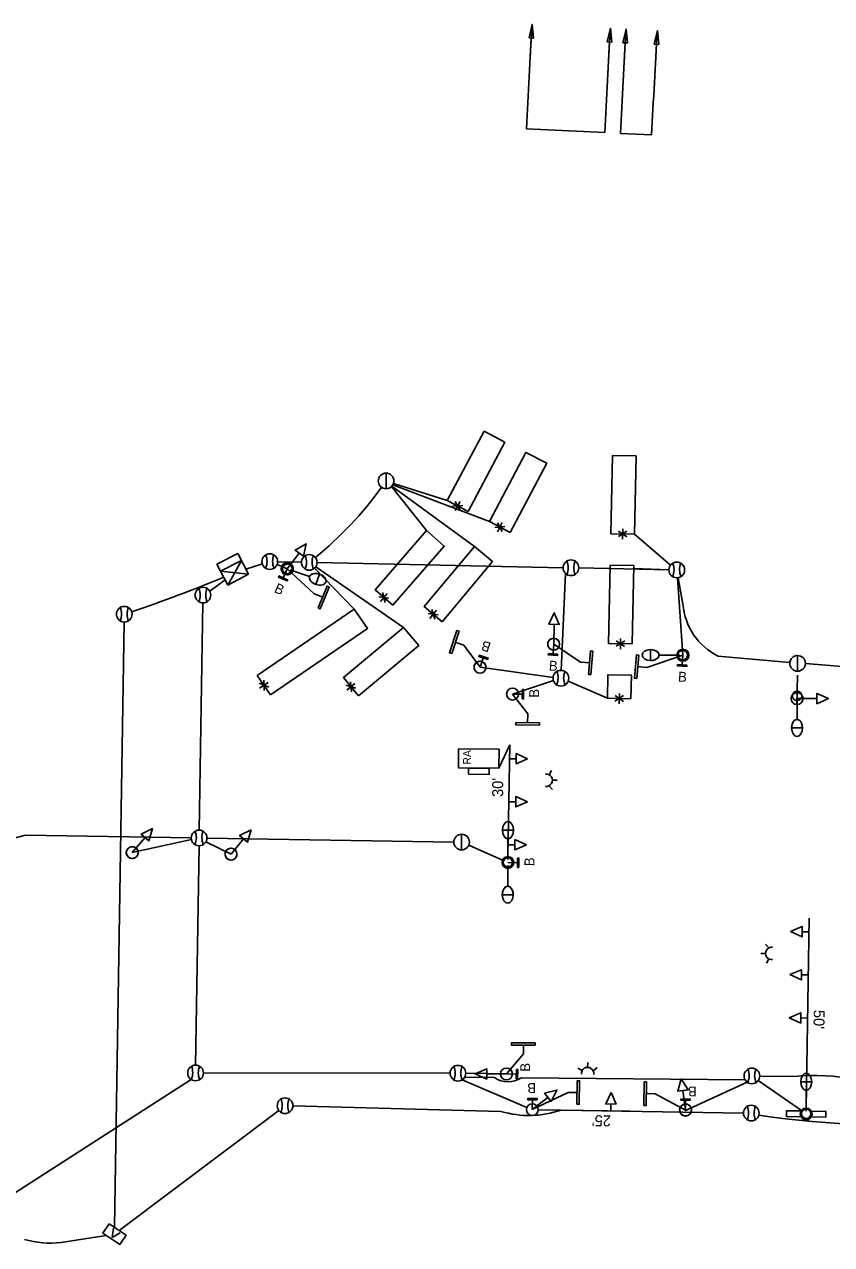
# Model space of a CAD drawing. Extents: x 596176 to 605330, y 332416 to 402398.
# Drawn here: x 602517.5 to 602723.5, y 366044.3 to 366355.8 of the extents above; entities that cross this region are included whole.
import ezdxf

# ---------------------------------------------------------------- set-up
doc = ezdxf.new("R2010")
doc.units = 0
for name, color, linetype in [('P_LTG', 7, 'Continuous'), ('P_SIG', 7, 'Continuous'), ('P_SIG_Bold', 7, 'Continuous'), ('P_SIG_Conduit', 7, 'Continuous'), ('P_SIG_IC', 7, 'Continuous'), ('P_SIG_Loops', 7, 'Continuous')]:
    doc.layers.add(name, color=color, linetype=linetype)

# ---------------------------------------------------------------- blocks, each defined once
blk = doc.blocks.new('_U322')
at = {"layer": 'P_LTG'}
for p, q in [((4.32, 25.12), (-4.14, 25.12)), ((0.05, 2.3), (0.05, 18.44))]:
    blk.add_line(p, q, dxfattribs=at)
blk.add_circle((0.05, 0.15), 3.68, dxfattribs=at)
blk.add_ellipse((0.09, 25.12), major_axis=(0, 6.65), ratio=0.636439, dxfattribs=at)
blk.add_ellipse((0.09, 25.12), major_axis=(0, 6.65), ratio=0.636439, start_param=1.570796, end_param=4.712389, dxfattribs=at)

msp = doc.modelspace()

# ---------------------------------------------------------------- linework, layer by layer
at = {"layer": 'P_SIG'}
for p, q in [((602609.8, 366241.29), (602609.78, 366237.29)), ((602566.64, 366218.02), (602571.96, 366220.79)), ((602566.64, 366218.02), (602571.96, 366220.79)), ((602567.56, 366216.24), (602572.88, 366219.01)), ((602567.56, 366216.24), (602572.88, 366219.01)), ((602569.41, 366212.7), (602572.88, 366219.01)), ((602569.41, 366212.7), (602572.88, 366219.01)), ((602571.96, 366220.79), (602574.73, 366215.46)), ((602571.96, 366220.79), (602574.73, 366215.46)), ((602587.64, 366220.85), (602584.56, 366216.84)), ((602569.41, 366212.7), (602566.64, 366218.02)), ((602569.41, 366212.7), (602566.64, 366218.02)), ((602574.73, 366215.46), (602567.56, 366216.24)), ((602574.73, 366215.46), (602567.56, 366216.24)), ((602584.56, 366216.84), (602583.55, 366214.55)), ((602591.47, 366210.49), (602584.56, 366216.84)), ((602574.73, 366215.46), (602569.41, 366212.7)), ((602574.73, 366215.46), (602569.41, 366212.7)), ((602591.47, 366210.49), (602593.69, 366209.57)), ((602652.66, 366202.66), (602652.57, 366197.61)), ((602629.66, 366197.38), (602627.39, 366198.16)), ((602629.66, 366197.38), (602633.78, 366191.72)), ((602652.57, 366197.61), (602652.4, 366195.11)), ((602659.4, 366193.02), (602652.57, 366197.61)), ((602633.78, 366191.72), (602634.58, 366194.08)), ((602676.31, 366191.69), (602685.53, 366194.79)), ((602685.53, 366194.79), (602685.35, 366192.3)), ((602714.81, 366194.71), (602714.79, 366190.71)), ((602659.4, 366193.02), (602661.79, 366192.82)), ((602676.31, 366191.69), (602673.92, 366191.91)), ((602642.06, 366184.86), (602644.56, 366184.82)), ((602645.93, 366179.8), (602642.06, 366184.86)), ((602719.73, 366183.7), (602714.67, 366183.71)), ((602645.93, 366179.8), (602645.9, 366177.4)), ((602638.59, 366165.97), (602641.35, 366171.87)), ((602642.96, 366168.37), (602641.19, 366168.37)), ((602651.41, 366164.25), (602652.01, 366165.33)), ((602652.24, 366162.88), (602653.47, 366162.88)), ((602651.39, 366161.46), (602652.27, 366160.47)), ((602642.9, 366157.37), (602641.12, 366157.37)), ((602548.29, 366148.26), (602545.03, 366144.39)), ((602573.45, 366147.89), (602570.23, 366143.99)), ((602629.08, 366149.07), (602629.06, 366145.07)), ((602642.67, 366146.4), (602640.89, 366146.4)), ((602640.85, 366141.86), (602643.35, 366141.81)), ((602715.96, 366124.18), (602717.73, 366124.15)), ((602707.46, 366120.06), (602706.58, 366121.05)), ((602706.62, 366118.65), (602705.39, 366118.65)), ((602707.44, 366117.27), (602706.84, 366116.2)), ((602715.78, 366113.18), (602717.55, 366113.16)), ((602715.61, 366102.18), (602717.38, 366102.16)), ((602644.88, 366092.97), (602644.88, 366095.37)), ((602644.88, 366092.97), (602640.52, 366087.87)), ((602659.84, 366088.75), (602658.77, 366089.35)), ((602661.23, 366089.55), (602661.24, 366090.78)), ((602662.63, 366088.69), (602663.63, 366089.56)), ((602635.47, 366087.89), (602640.52, 366087.87)), ((602640.52, 366087.87), (602643.02, 366087.79)), ((602656.25, 366083.15), (602647.11, 366078.76)), ((602651.08, 366081.9), (602647.11, 366078.76)), ((602656.25, 366083.15), (602658.65, 366083.11)), ((602678.49, 366082.84), (602676.09, 366082.87)), ((602678.49, 366082.84), (602686.22, 366078.65)), ((602685.53, 366083.66), (602686.22, 366078.65)), ((602647.11, 366078.76), (602647.16, 366081.26)), ((602667.16, 366080.2), (602667.12, 366078.43)), ((602686.22, 366078.65), (602686.22, 366081.15)), ((602540.22, 366048.47), (602539.86, 366046.09)), ((602541.94, 366047.3), (602539.86, 366046.09))]:
    msp.add_line(p, q, dxfattribs=at)
for points in [[(602609.78, 366237.29), (602609.8, 366241.29)], [(602589.44, 366223.2), (602588.69, 366220.05), (602586.59, 366221.65), (602589.44, 366223.2)], [(602588.69, 366220.05), (602589.44, 366223.2), (602586.59, 366221.65), (602588.69, 366220.05)], [(602652.7, 366205.62), (602653.97, 366202.65), (602651.34, 366202.68), (602652.7, 366205.62)], [(602653.97, 366202.65), (602652.7, 366205.62), (602651.34, 366202.68), (602653.97, 366202.65)], [(602714.79, 366190.71), (602714.81, 366194.71)], [(602722.69, 366183.7), (602719.73, 366182.38), (602719.73, 366185.02), (602722.69, 366183.7)], [(602719.73, 366182.38), (602722.69, 366183.7), (602719.73, 366185.02), (602719.73, 366182.38)], [(602550.19, 366150.52), (602549.3, 366147.41), (602547.28, 366149.11), (602550.19, 366150.52)], [(602549.3, 366147.41), (602550.19, 366150.52), (602547.28, 366149.11), (602549.3, 366147.41)], [(602575.33, 366150.18), (602574.47, 366147.06), (602572.43, 366148.73), (602575.33, 366150.18)], [(602574.47, 366147.06), (602575.33, 366150.18), (602572.43, 366148.73), (602574.47, 366147.06)], [(602629.06, 366145.07), (602629.08, 366149.07)], [(602632.51, 366087.89), (602635.47, 366089.2), (602635.47, 366086.57), (602632.51, 366087.89)], [(602635.47, 366089.2), (602632.51, 366087.89), (602635.47, 366086.57), (602635.47, 366089.2)], [(602685.12, 366086.59), (602686.84, 366083.84), (602684.23, 366083.48), (602685.12, 366086.59)], [(602686.84, 366083.84), (602685.12, 366086.59), (602684.23, 366083.48), (602686.84, 366083.84)], [(602653.4, 366083.74), (602651.9, 366080.87), (602650.26, 366082.93), (602653.4, 366083.74)], [(602653.4, 366083.74), (602651.9, 366080.87), (602650.26, 366082.93), (602653.4, 366083.74)], [(602651.9, 366080.87), (602653.4, 366083.74), (602650.26, 366082.93), (602651.9, 366080.87)]]:
    msp.add_lwpolyline(points, dxfattribs=at)
for points in [[(602582.45, 366215.04), (602584.65, 366214.07), (602584.52, 366213.77), (602582.32, 366214.74)], [(602592.43, 366206.89), (602594.73, 366212.43), (602595.29, 366212.2), (602592.98, 366206.66)], [(602628.46, 366200.91), (602626.54, 366195.23), (602625.97, 366195.42), (602627.89, 366201.11)], [(602635.72, 366193.7), (602633.45, 366194.47), (602633.55, 366194.78), (602635.83, 366194.01)], [(602651.2, 366195.19), (602653.6, 366195.03), (602653.57, 366194.71), (602651.18, 366194.87)], [(602661.41, 366189.89), (602661.92, 366195.86), (602662.52, 366195.81), (602662.01, 366189.83)], [(602674.31, 366194.84), (602673.78, 366188.86), (602673.18, 366188.92), (602673.72, 366194.89)], [(602684.16, 366192.39), (602686.55, 366192.22), (602686.53, 366191.89), (602684.13, 366192.06)], [(602644.55, 366183.62), (602644.58, 366186.02), (602644.9, 366186.02), (602644.87, 366183.62)], [(602642.94, 366177.58), (602648.94, 366177.49), (602648.93, 366176.89), (602642.93, 366176.98)], [(602638.62, 366170.79), (602628.28, 366170.86), (602628.24, 366166.04), (602638.59, 366165.97)], [(602645.92, 366168.37), (602642.96, 366167.06), (602642.96, 366169.69)], [(602630.86, 366164.39), (602630.87, 366165.99), (602636.14, 366165.95), (602636.13, 366164.35)], [(602645.85, 366157.37), (602642.9, 366156.06), (602642.9, 366158.69)], [(602645.62, 366146.4), (602642.67, 366145.09), (602642.67, 366147.72)], [(602643.33, 366140.61), (602643.37, 366143.01), (602643.7, 366143.01), (602643.66, 366140.61)], [(602713, 366124.23), (602715.98, 366125.5), (602715.94, 366122.87)], [(602712.82, 366113.23), (602715.8, 366114.5), (602715.76, 366111.87)], [(602712.65, 366102.23), (602715.63, 366103.5), (602715.59, 366100.87)], [(602647.84, 366095.24), (602641.84, 366095.23), (602641.84, 366095.83), (602647.84, 366095.83)], [(602642.98, 366086.59), (602643.06, 366088.98), (602643.39, 366088.97), (602643.3, 366086.58)], [(602658.47, 366080.15), (602658.56, 366086.15), (602659.16, 366086.14), (602659.07, 366080.14)], [(602676.27, 366085.83), (602676.18, 366079.83), (602675.58, 366079.84), (602675.67, 366085.84)], [(602667.22, 366083.16), (602668.47, 366080.17), (602665.84, 366080.23)], [(602648.36, 366081.24), (602645.96, 366081.29), (602645.97, 366081.61), (602648.37, 366081.57)], [(602687.42, 366081.15), (602685.02, 366081.15), (602685.02, 366081.47), (602687.42, 366081.47)], [(602539.15, 366049.65), (602543.46, 366046.71), (602541.82, 366044.31), (602537.51, 366047.24)]]:
    msp.add_lwpolyline(points, close=True, dxfattribs=at)
for centre, radius in [((602609.79, 366239.29), 2), ((602580.13, 366218.7), 2), ((602590.19, 366218.49), 2), ((602656.98, 366217.11), 2), ((602584.56, 366216.84), 1.52), ((602584.56, 366216.84), 1.52), ((602584.56, 366216.84), 1.52), ((602683.98, 366216.55), 2), ((602563.07, 366210.14), 2), ((602542.99, 366205.26), 2), ((602652.57, 366197.61), 1.52), ((602652.57, 366197.61), 1.52), ((602652.57, 366197.61), 1.52), ((602685.53, 366194.79), 1.52), ((602714.8, 366192.71), 2), ((602633.78, 366191.72), 1.52), ((602654.4, 366188.92), 2), ((602642.06, 366184.86), 1.52), ((602714.67, 366183.71), 1.52), ((602714.67, 366183.71), 1.52), ((602714.67, 366183.71), 1.52), ((602562.09, 366148.13), 2), ((602629.07, 366147.07), 2), ((602545.03, 366144.39), 1.52), ((602545.03, 366144.39), 1.52), ((602545.03, 366144.39), 1.52), ((602570.23, 366143.99), 1.52), ((602570.23, 366143.99), 1.52), ((602570.23, 366143.99), 1.52), ((602561.17, 366088.13), 2), ((602628.14, 366088.07), 2), ((602640.52, 366087.87), 1.52), ((602640.52, 366087.87), 1.52), ((602640.52, 366087.87), 1.52), ((602703.14, 366087.38), 2), ((602584.01, 366079.77), 2), ((602686.22, 366078.65), 1.52), ((602686.22, 366078.65), 1.52), ((602686.22, 366078.65), 1.52), ((602702.99, 366077.89), 2)]:
    msp.add_circle(centre, radius, dxfattribs=at)
for centre, radius, start, end in [((602609.79, 366239.29), 2, 89.7008, 180), ((602609.79, 366239.29), 2, 180, 269.7008), ((602575.06, 366218.74), 4.36, 336.6741, 22.5272), ((602585.2, 366218.75), 4.36, 157.5751, 203.4282), ((602585.12, 366218.52), 4.36, 336.6741, 22.5272), ((602595.26, 366218.53), 4.36, 157.5751, 203.4282), ((602651.91, 366217.14), 4.36, 336.6741, 22.5272), ((602662.05, 366217.15), 4.36, 157.5751, 203.4282), ((602584.56, 366216.84), 1.52, 52.6073, 232.6073), ((602584.56, 366216.84), 1.52, 232.6073, 52.6073), ((602678.91, 366216.58), 4.36, 336.6741, 22.5272), ((602689.05, 366216.59), 4.36, 157.5751, 203.4282), ((602558, 366210.18), 4.36, 336.6741, 22.5272), ((602568.14, 366210.19), 4.36, 157.5751, 203.4282), ((602537.92, 366205.29), 4.36, 336.6741, 22.5272), ((602548.06, 366205.3), 4.36, 157.5751, 203.4282), ((602652.57, 366197.61), 1.52, 89.1897, 269.1897), ((602652.57, 366197.61), 1.52, 269.1897, 89.1897), ((602685.53, 366194.79), 1.52, 0, 180), ((602685.53, 366194.79), 1.52, 180, 0), ((602714.8, 366192.71), 2, 89.7008, 180), ((602633.78, 366191.72), 1.52, 89.1897, 269.1897), ((602633.78, 366191.72), 1.52, 269.1897, 89.1897), ((602714.8, 366192.71), 2, 180, 269.7008), ((602649.33, 366188.96), 4.36, 336.6741, 22.5272), ((602659.47, 366188.97), 4.36, 157.5751, 203.4282), ((602642.06, 366184.86), 1.52, 0, 180), ((602642.06, 366184.86), 1.52, 180, 0), ((602714.67, 366183.71), 1.52, 0, 180), ((602714.67, 366183.71), 1.52, 180, 0), ((602650.66, 366162.86), 1.58, 262.3317, 97.8392), ((602557.02, 366148.16), 4.36, 336.6741, 22.5272), ((602567.16, 366148.17), 4.36, 157.5751, 203.4282), ((602629.07, 366147.07), 2, 89.7008, 180), ((602545.03, 366144.39), 1.52, 49.9699, 229.9699), ((602545.03, 366144.39), 1.52, 229.9699, 49.9699), ((602570.23, 366143.99), 1.52, 50.5662, 230.5662), ((602570.23, 366143.99), 1.52, 230.5662, 50.5662), ((602629.07, 366147.07), 2, 180, 269.7008), ((602708.19, 366118.66), 1.58, 82.3317, 277.8392), ((602556.1, 366088.17), 4.36, 336.6741, 22.5272), ((602566.24, 366088.18), 4.36, 157.5751, 203.4282), ((602623.07, 366088.11), 4.36, 336.6741, 22.5272), ((602633.21, 366088.12), 4.36, 157.5751, 203.4282), ((602640.52, 366087.87), 1.52, 0, 180), ((602661.22, 366087.98), 1.58, 351.7096, 187.2171), ((602698.07, 366087.42), 4.36, 336.6741, 22.5272), ((602708.21, 366087.42), 4.36, 157.5751, 203.4282), ((602640.52, 366087.87), 1.52, 180, 0), ((602578.94, 366079.81), 4.36, 336.6741, 22.5272), ((602589.08, 366079.82), 4.36, 157.5751, 203.4282), ((602686.22, 366078.65), 1.52, 97.9663, 277.9663), ((602686.22, 366078.65), 1.52, 277.9663, 97.9663), ((602697.92, 366077.92), 4.36, 336.6741, 22.5272), ((602708.06, 366077.93), 4.36, 157.5751, 203.4282)]:
    msp.add_arc(centre, radius, start, end, dxfattribs=at)
at = {"layer": 'P_SIG_Bold'}
for p, q in [((602641.35, 366171.87), (602640.9, 366143.37)), ((602717.01, 366079.16), (602717.78, 366127.65)), ((602672.11, 366078.37), (602648.61, 366078.74))]:
    msp.add_line(p, q, dxfattribs=at)
for points in [[(602715.68, 366076.93), (602711.98, 366076.99), (602712, 366078.49), (602715.7, 366078.43)], [(602718.3, 366078.39), (602722, 366078.33), (602721.98, 366076.83), (602718.28, 366076.89)]]:
    msp.add_lwpolyline(points, dxfattribs=at)
for centre in [(602640.88, 366141.87), (602647.11, 366078.76), (602716.99, 366077.66)]:
    msp.add_circle(centre, 1.5, dxfattribs=at)
at = {"layer": 'P_SIG_Conduit'}
for p, q in [((602574.04, 366216.79), (602578.23, 366218.1)), ((602581.98, 366217.93), (602584.56, 366216.84)), ((602588.19, 366218.53), (602582.13, 366218.66)), ((602654.98, 366217.14), (602592.19, 366218.45)), ((602681.98, 366216.58), (602658.98, 366217.06)), ((602564.81, 366211.13), (602568.7, 366214.05)), ((602655.59, 366215.67), (602654.44, 366190.9)), ((602563.04, 366208.14), (602562.12, 366150.13)), ((602652.4, 366189.09), (602633.78, 366191.72)), ((602652.49, 366188.32), (602642.06, 366184.86)), ((602560.13, 366147.7), (602545.03, 366144.39)), ((602627.07, 366147.09), (602564.09, 366148.09)), ((602562.06, 366146.13), (602561.2, 366090.13)), ((602563.8, 366147.1), (602570.23, 366143.99)), ((602630.92, 366146.29), (602639.51, 366142.48)), ((602563.17, 366088.13), (602626.14, 366088.1)), ((602560.08, 366086.45), (602509.25, 366053.76)), ((602686, 366078.42), (602701.95, 366085.78)), ((602704.78, 366086.23), (602715.76, 366078.52))]:
    msp.add_line(p, q, dxfattribs=at)
for points in [[(602684.12, 366214.55), (602685.53, 366194.79)], [(602684.33, 366214.58), (602685.53, 366207.83)], [(602694.5, 366194.53), (602712.82, 366192.97)], [(602716.8, 366192.63), (602745.78, 366190.29)], [(602714.77, 366189.71), (602714.65, 366182.21)], [(602488.97, 366141.28), (602517.76, 366148.83), (602560.09, 366148.16)], [(602640.52, 366087.87), (602630.14, 366088.04)], [(602645.73, 366079.35), (602629.22, 366086.38)], [(602629.86, 366087.04), (602637.43, 366086.97)], [(602644.35, 366086.91), (602701.4, 366086.39)], [(602705.14, 366087.35), (602713.86, 366087.21)]]:
    msp.add_lwpolyline(points, dxfattribs=at)
for centre, radius, start, end in [((602532.12, 366292.92), 94.4, 309.1709, 324.1581), ((602701.86, 366209.17), 16.38, 184.6971, 243.3135), ((602640.94, 366091.93), 6.07, 234.7371, 304.2288), ((602719.11, 366039.94), 47.57, 57.9898, 96.3464)]:
    msp.add_arc(centre, radius, start, end, dxfattribs=at)
at = {"layer": 'P_SIG_IC'}
for points in [[(602540.51, 366048.72), (602542.96, 366203.24)], [(602586.01, 366079.74), (602639.12, 366078.31)], [(602654.51, 366078.65), (602700.99, 366077.88)], [(602541.71, 366047.9), (602582.41, 366078.57)], [(602526.86, 366044.85), (602538.38, 366046.65)]]:
    msp.add_lwpolyline(points, dxfattribs=at)
for centre, radius, start, end in [((602419.22, 366576.86), 391.68, 288.7142, 292.3828), ((602646.29, 366102.42), 25.15, 253.4339, 289.078), ((602737.84, 366297.84), 222.95, 261.5069, 275.5534), ((602524.06, 366068.51), 23.82, 254.0384, 276.7577)]:
    msp.add_arc(centre, radius, start, end, dxfattribs=at)
at = {"layer": 'P_SIG_Loops'}
for p, q in [((602620.1, 366226.59), (602611.17, 366237.84)), ((602632.32, 366222.55), (602611.24, 366237.91)), ((602636.17, 366228.89), (602611.54, 366238.33)), ((602625.42, 366234.33), (602611.67, 366238.62)), ((602629.37, 366233.05), (602626.78, 366232.81)), ((602627.44, 366231.7), (602628.69, 366234.06)), ((602628.7, 366231.76), (602627.44, 366234.03)), ((602628.06, 366232.92), (602630.71, 366231.51)), ((602638.2, 366226.27), (602639.45, 366228.64)), ((602639.46, 366226.34), (602638.2, 366228.6)), ((602640.13, 366227.63), (602637.54, 366227.38)), ((602638.82, 366227.49), (602641.48, 366226.09)), ((602671.27, 366226.47), (602669.07, 366225.08)), ((602671.26, 366225.01), (602669.11, 366226.47)), ((602670.16, 366224.38), (602670.21, 366227.06)), ((602670.17, 366225.76), (602673.17, 366225.7)), ((602673.15, 366225.68), (602682.4, 366217.77)), ((602681.98, 366216.62), (602673, 366216.94)), ((602610.54, 366209.37), (602607.96, 366209.72)), ((602608.35, 366208.49), (602610.1, 366210.51)), ((602609.59, 366208.27), (602608.88, 366210.76)), ((602609.23, 366209.53), (602611.5, 366207.57)), ((602622.21, 366204.01), (602621.44, 366206.48)), ((602623.13, 366205.13), (602620.55, 366205.43)), ((602620.96, 366204.2), (602622.67, 366206.26)), ((602621.82, 366205.27), (602624.13, 366203.35)), ((602670.69, 366198.46), (602668.49, 366197.07)), ((602670.67, 366197), (602668.53, 366198.46)), ((602669.58, 366196.37), (602669.63, 366199.05)), ((602669.59, 366197.75), (602672.59, 366197.68)), ((602577.5, 366186.34), (602579.71, 366187.85)), ((602578.65, 366185.81), (602578.58, 366188.4)), ((602601, 366185.44), (602600.69, 366188.01)), ((602579.84, 366186.64), (602577.44, 366187.62)), ((602578.62, 366187.13), (602580.32, 366184.65)), ((602602.11, 366186.38), (602599.62, 366187.14)), ((602599.8, 366185.86), (602601.86, 366187.58)), ((602600.84, 366186.75), (602602.77, 366184.45)), ((602669.28, 366182.38), (602669.34, 366185.05)), ((602670.4, 366184.46), (602668.2, 366183.07)), ((602670.38, 366183.01), (602668.24, 366184.46)), ((602669.3, 366183.75), (602672.29, 366183.69))]:
    msp.add_line(p, q, dxfattribs=at)
for points in [[(602646.28, 366352.39), (602647.06, 366355.85), (602647.44, 366352.32)], [(602666.25, 366351.42), (602667.04, 366354.88), (602667.42, 366351.35)], [(602670.25, 366351.18), (602671.03, 366354.64), (602671.41, 366351.12)], [(602678.24, 366350.82), (602679.02, 366354.28), (602679.4, 366350.75)], [(602630.71, 366231.51), (602640.1, 366249.17), (602634.81, 366251.98), (602625.42, 366234.33)], [(602641.48, 366226.09), (602650.8, 366243.78), (602645.5, 366246.58), (602636.17, 366228.89)], [(602673.17, 366225.7), (602673.58, 366245.69), (602667.58, 366245.82), (602667.17, 366225.82)], [(602611.5, 366207.57), (602624.63, 366222.65), (602620.1, 366226.59), (602606.97, 366211.51)], [(602624.13, 366203.35), (602636.93, 366218.71), (602632.32, 366222.55), (602619.52, 366207.19)], [(602672.59, 366197.68), (602673, 366217.68), (602667, 366217.8), (602666.59, 366197.81)], [(602580.32, 366184.65), (602605.06, 366201.62), (602601.67, 366206.57), (602576.93, 366189.6)], [(602602.77, 366184.45), (602618.12, 366197.27), (602614.27, 366201.87), (602598.92, 366189.06)], [(602672.29, 366183.69), (602672.42, 366189.69), (602666.42, 366189.81), (602666.3, 366183.81)]]:
    msp.add_lwpolyline(points, close=True, dxfattribs=at)
for points in [[(602646.86, 366352.35), (602646.56, 366347.29)], [(602666.83, 366351.39), (602666.54, 366346.32)], [(602670.83, 366351.15), (602670.53, 366346.09)], [(602678.82, 366350.78), (602678.53, 366345.72)], [(602645.61, 366329.22), (602665.58, 366328.22)], [(602669.58, 366328.02), (602677.57, 366327.62)], [(602601.67, 366206.57), (602591.57, 366217.05)], [(602614.27, 366201.87), (602591.83, 366217.35)], [(602656.24, 366188.13), (602666.3, 366183.81)]]:
    msp.add_lwpolyline(points, dxfattribs=at)
for centre, radius in [((605648.83, 366178.55), 3007), ((605672.8, 366177.34), 3011), ((605672.8, 366177.34), 3007), ((605684.78, 366176.74), 3011)]:
    msp.add_arc(centre, radius, 176.61975, 177.12785, dxfattribs=at)

# ---------------------------------------------------------------- block references
at = {"layer": 'P_LTG', "xscale": 0.32808333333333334}
for p, yscale, rotation in [((602584.56, 366216.84), 0.3280833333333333, -108.71801817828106), ((602685.53, 366194.79), 0.32808333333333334, 90), ((602714.69, 366184.46), 0.32808333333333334, 180), ((602640.88, 366141.87), 0.32808333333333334, 180)]:
    msp.add_blockref('_U322', p, dxfattribs=dict(at, yscale=yscale, rotation=rotation))
at = {"layer": 'P_LTG', "xscale": 0.32808333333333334, "yscale": 0.32808333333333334}
for p in [(602640.88, 366141.87), (602716.99, 366077.66)]:
    msp.add_blockref('_U322', p, dxfattribs=at)

# ---------------------------------------------------------------- texts
at = {"layer": 'P_SIG'}
for s, height, rotation, p in [('B', 2.52, 336.2727, (602581.06, 366210.98)), ('B', 2.52, 161.282, (602636.75, 366197.86)), ('B', 2.52, 356.1527, (602651.27, 366190.91)), ('B', 2.52, 356.0144, (602684.22, 366188.1)), ('B', 2.52, 89.2055, (602648.82, 366183.92)), ('RA', 2, 89.6023, (602631.44, 366166.84)), ('B', 2.52, 89.0401, (602647.61, 366140.9)), ("50'", 2.8, 269.0919, (602718.93, 366104.25)), ('B', 2.52, 90, (602646.55, 366088.46)), ('B', 2.52, 178.9029, (602648.08, 366085.52)), ('B', 2.52, 180, (602689.06, 366084.65))]:
    msp.add_text(s, height=height, rotation=rotation, dxfattribs=at).set_placement(p)
at = {"layer": 'P_SIG_Bold'}
for s, rotation, p in [("30'", 90, (602639.67, 366158.6)), ("25'", 179.0919, (602667.2, 366077.28))]:
    msp.add_text(s, height=2.8, rotation=rotation, dxfattribs=at).set_placement(p)

doc.saveas('drawing.dxf')
